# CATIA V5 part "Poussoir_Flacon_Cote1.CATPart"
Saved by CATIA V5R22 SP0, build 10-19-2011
Part number: Poussoir_Flacon_Cote1
Bounding box of the stored display mesh (mm): x 0 to 5, y -82.5 to 97.5, z -24.5 to 24.5
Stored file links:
  C:\Users\La forge\Desktop\CAO_PER_pick&place_2023A\Sous_Ensemble_Flacon\Verin\Poussoir_Flacon\Poussoir_Flacon_Cote1.CATPart
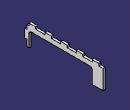
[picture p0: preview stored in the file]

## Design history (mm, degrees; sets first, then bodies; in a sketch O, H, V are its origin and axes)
Body1 (main body)
  Sketch1 on yz-plane, origin (0, 0, 0), H (0, 1, 0), V (0, 0, 1)
    line L1 (97.5, -24.5) -> (72.5, -24.5)
    line L2 (-82.5, -24.5) -> (-82.5, 24.5)
    line L3 (-82.5, 24.5) -> (97.5, 24.5)
    line L4 (97.5, 24.5) -> (97.5, -24.5)
    point P5 (72.5, -24.5)
    line L5 (-72.5, -24.5) -> (-72.5, 4.5)
    line L6 (-67.5, 9.5) -> (67.5, 9.5)
    line L7 (72.5, 4.5) -> (72.5, -24.5)
    point P7 (72.5, 9.5)
    line L8 (-72.5, -24.5) -> (-82.5, -24.5)
    arc A1 centre (-67.5, 4.5) radius 5 from (-72.5, 4.5) to (-67.5, 9.5) cw
    arc A2 centre (67.5, 4.5) radius 5 from (72.5, 4.5) to (67.5, 9.5) ccw
    length L3 = 180
    length L4 = 49
    distance L7 L4 = 25
    radius A1 = 5
    distance P7 P5 = 34
    radius A2 = 5
    distance L5 L2 = 10
    horizontal: L1 H, L3 H, L6 H, L8 H
    vertical: L2 V, L4 V, L5 V, L7 V
    equidistance: L1 L3 O, L7 L5 O
    coincidence: L1 L8, L7 P7, L6 P7
    tangency: A1 L5, A1 L6, A2 L7, A2 L6
  Pad1: profile Sketch1, direction (1, 0, 0), length 5
  Sketch2 on end face of Pad1, origin (5, 0, 0), H (0, 1, 0), V (0, 0, 1)
    point P1 (-82.5, -24.5)
    line L1 (-82.5, -24.5) -> (-77.5, -24.5)
    line L2 (-77.5, -24.5) -> (-77.5, -9.5)
    line L3 (-77.5, -9.5) -> (-82.5, -9.5)
    line L4 (-82.5, -9.5) -> (-82.5, -24.5)
    point P2 (-77.5, -24.5)
    point P3 (-77.5, -9.5)
    point P4 (-82.5, -9.5)
    reference projected line E1 (-82.5, -24.5) -> (-72.5, -24.5) from edge [face of Pad1 from Sketch1.L8 | end face of Pad1]
    reference projected line E2 (-82.5, 24.5) -> (-82.5, -24.5) from edge [face of Pad1 from Sketch1.L2 | end face of Pad1]
    point P5 (-82.5, 24.5)
    point P6 (-77.5, 24.5)
    point P7 (-77.5, 9.5)
    point P8 (-82.5, 9.5)
    line L5 (-82.5, 24.5) -> (-77.5, 24.5)
    line L6 (-77.5, 24.5) -> (-77.5, 9.5)
    line L7 (-77.5, 9.5) -> (-82.5, 9.5)
    line L8 (-82.5, 9.5) -> (-82.5, 24.5)
    distance L1 E1 = 0
    distance L4 E2 = 0
    length L3 = 5
    length L2 = 15
    horizontal: L1 H, L3 H
    vertical: L2 V, L4 V
    symmetry: P1 P5 H, P2 P6 H, P3 P7 H, P4 P8 H, L1 L5 H, L2 L6 H, L3 L7 H, L4 L8 H
  Pocket1: profile Sketch2, direction (-1, 0, 0), through (limit type 6)
  Sketch3 on end face of Pad1, origin (5, 0, 0), H (0, 1, 0), V (0, 0, 1)
    line L1 (87.5, 24.5) -> (97.5, 24.5)
    line L2 (97.5, 24.5) -> (97.5, 19.5)
    line L3 (97.5, 19.5) -> (87.5, 19.5)
    line L4 (87.5, 19.5) -> (87.5, 24.5)
    reference projected line E1 (97.5, 24.5) -> (-82.5, 24.5) from edge [face of Pad1 from Sketch1.L3 | end face of Pad1]
    reference projected line E2 (97.5, -24.5) -> (97.5, 24.5) from edge [face of Pad1 from Sketch1.L4 | end face of Pad1]
    point P5 (51.25, 24.5)
    line L5 (51.25, 24.5) -> (72.5, 24.5)
    line L6 (72.5, 24.5) -> (72.5, 20)
    line L7 (72.5, 20) -> (51.25, 20)
    line L8 (51.25, 20) -> (51.25, 24.5)
    reference projected line E3 (-67.5, 9.5) -> (67.5, 9.5) from edge [face of Pad1 from Sketch1.L6 | end face of Pad1]
    point P9 (15, 24.5)
    line L9 (15, 24.5) -> (36.25, 24.5)
    line L10 (36.25, 24.5) -> (36.25, 19.5)
    line L11 (36.25, 19.5) -> (15, 19.5)
    line L12 (15, 19.5) -> (15, 24.5)
    point P11 (36.25, 19.5)
    point P13 (-21.25, 24.5)
    line L13 (-21.25, 24.5) -> (0, 24.5)
    line L14 (0, 24.5) -> (0, 19.5)
    line L15 (0, 19.5) -> (-21.25, 19.5)
    line L16 (-21.25, 19.5) -> (-21.25, 24.5)
    point P15 (0, 19.5)
    point P17 (-57.5, 24.5)
    line L17 (-57.5, 24.5) -> (-36.25, 24.5)
    line L18 (-36.25, 24.5) -> (-36.25, 20)
    line L19 (-36.25, 20) -> (-57.5, 20)
    line L20 (-57.5, 20) -> (-57.5, 24.5)
    point P19 (-36.25, 20)
    line L21 (-72.5, 24.5) -> (-77.5, 24.5)
    line L22 (-77.5, 24.5) -> (-77.5, 19.5)
    line L23 (-77.5, 19.5) -> (-72.5, 19.5)
    line L24 (-72.5, 19.5) -> (-72.5, 24.5)
    point P22 (-77.5, 24.5)
    reference projected point E4 (-77.5, 24.5) from vertex [face of Pad1 from Sketch1.L3 | face of Pocket1 from Sketch2.L6 | end face of Pad1]
    length L2 = 5
    length L3 = 10
    distance L6 L4 = 15
    length L7 = 21.25
    distance L7 E3 = 10.5
    distance L10 L8 = 15
    length L11 = 21.25
    length L15 = 21.25
    distance L14 L12 = 15
    distance L18 L16 = 15
    length L19 = 21.25
    length L22 = 5
    distance L20 L24 = 15
    horizontal: L1 H, L3 H, L5 H, L7 H, L9 H, L11 H, L13 H, L15 H, L17 H, L19 H, L21 H, L23 H
    vertical: L2 V, L4 V, L6 V, L8 V, L10 V, L12 V, L14 V, L16 V, L18 V, L20 V, L22 V, L24 V
    coincidence: L1 E1, L2 E2, P5 L1, P9 L1, P11 L3, P13 L1, P15 L3, P17 L1, P19 L7, E4 P22
  Pocket2: profile Sketch3, direction (-1, 0, 0), through (limit type 6)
